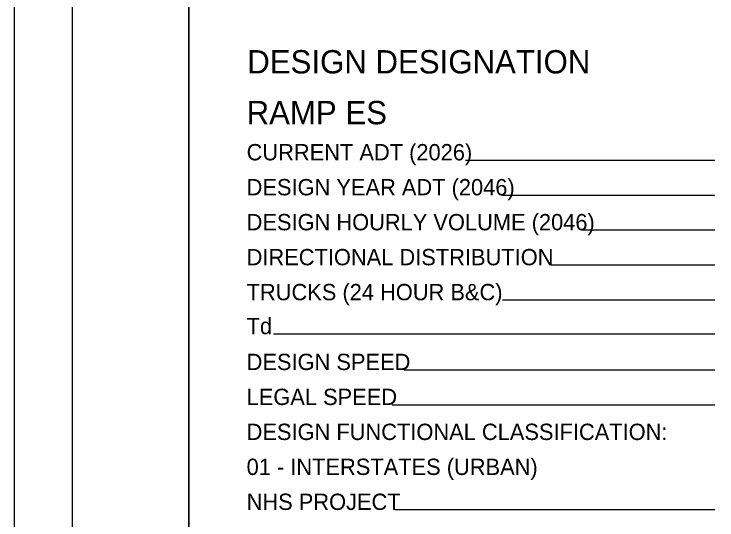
# Model space of a CAD drawing. Extents: x 0 to 34, y -1.2 to 22.
# Drawn here: x 0 to 6.03, y 6.56 to 10.9 of the extents above; entities that cross this region are included whole.
import ezdxf

# ---------------------------------------------------------------- set-up
doc = ezdxf.new("R2010")
doc.units = 0
for name, color, linetype in [('SH_Border', 7, 'Continuous'), ('SH_Cut_Line', 7, 'Continuous'), ('SH_Data', 7, 'Continuous')]:
    doc.layers.add(name, color=color, linetype=linetype)

msp = doc.modelspace()

# ---------------------------------------------------------------- linework, layer by layer
at = {"layer": 'SH_Border'}
for points in [[(0.5, 21.5), (1.5, 21.5), (1.5, 0.5), (0.5, 0.5)], [(1.5, 21.5), (33.5, 21.5), (33.5, 0.5), (1.5, 0.5)]]:
    msp.add_lwpolyline(points, close=True, dxfattribs=at)
at = {"layer": 'SH_Cut_Line'}
msp.add_lwpolyline([(0, 0), (34, 0), (34, 22), (0, 22)], close=True, dxfattribs=at)
at = {"layer": 'SH_Data'}
for p, q in [((6.0092, 9.6429), (3.8711, 9.6429)), ((6.0092, 9.3429), (4.1886, 9.3429)), ((6.0092, 9.0429), (4.8724, 9.0429)), ((6.0092, 8.7429), (4.6037, 8.7429)), ((6.0092, 8.4429), (4.1886, 8.4429)), ((6.0092, 8.1519), (2.2248, 8.1519)), ((6.0092, 7.8442), (3.346, 7.8442)), ((6.0092, 7.5442), (3.2422, 7.5442)), ((6.0092, 6.6442), (3.267, 6.6442))]:
    msp.add_line(p, q, dxfattribs=at)

# ---------------------------------------------------------------- texts
at = {"layer": 'SH_Cut_Line'}
for s, height, p in [('RAMP ES', 0.2, (1.9945, 9.9527)), ('CURRENT ADT (2026)', 0.14, (1.9945, 9.6429)), ('DESIGN YEAR ADT (2046)', 0.14, (1.9945, 9.3429)), ('DESIGN HOURLY VOLUME (2046)', 0.14, (1.9945, 9.0429)), ('DIRECTIONAL DISTRIBUTION', 0.14, (1.9945, 8.7429)), ('TRUCKS (24 HOUR B&C)', 0.14, (1.9945, 8.4429)), ('Td', 0.14, (1.9945, 8.1519)), ('DESIGN SPEED', 0.14, (1.9945, 7.8442)), ('LEGAL SPEED', 0.14, (1.9945, 7.5442)), ('DESIGN FUNCTIONAL CLASSIFICATION:', 0.14, (1.9945, 7.2442)), ('01 - INTERSTATES (URBAN)', 0.14, (1.9945, 6.9442)), ('NHS PROJECT', 0.14, (1.9945, 6.6442))]:
    msp.add_text(s, height=height, dxfattribs=at).set_placement(p)
at = {"layer": 'SH_Data'}
msp.add_text('DESIGN DESIGNATION', height=0.2, dxfattribs=at).set_placement((2.0001, 10.3885))

doc.saveas('drawing.dxf')
